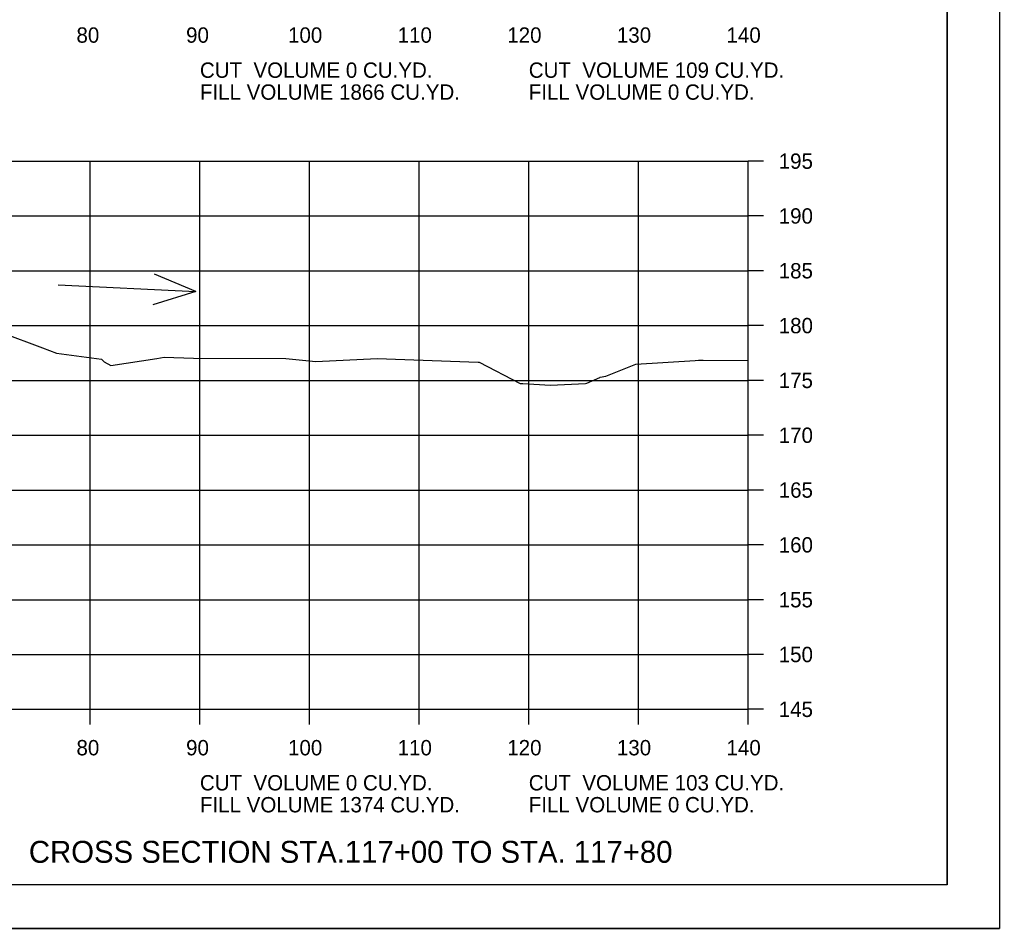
# Model space of a CAD drawing. Extents: x 915787 to 919910, y 133456 to 136717.
# Drawn here: x 916487.5 to 916576.9, y 135376.1 to 135459 of the extents above; entities that cross this region are included whole.
import ezdxf

# ---------------------------------------------------------------- set-up
doc = ezdxf.new("R2010")
doc.units = 0
for name, color, linetype in [('R_Axis', 7, 'Continuous'), ('R_Axis Annot', 7, 'Continuous'), ('R_Border', 7, 'Continuous'), ('R_Border Notes', 7, 'Continuous'), ('R_Draft', 7, 'Continuous'), ('R_Exist Surface', 7, 'Continuous'), ('R_Grid', 7, 'Continuous'), ('R_No Plot', 7, 'Continuous'), ('R_Water Annot', 7, 'Continuous')]:
    doc.layers.add(name, color=color, linetype=linetype)

msp = doc.modelspace()

# ---------------------------------------------------------------- linework, layer by layer
at = {"layer": 'R_Axis'}
for p, q in [((916553.975, 135396.057), (916553.975, 135446.057)), ((916555.375, 135446.057), (916553.975, 135446.057)), ((916555.375, 135441.057), (916553.975, 135441.057)), ((916555.375, 135436.057), (916553.975, 135436.057)), ((916555.375, 135431.057), (916553.975, 135431.057)), ((916555.375, 135426.057), (916553.975, 135426.057)), ((916555.375, 135421.057), (916553.975, 135421.057)), ((916555.375, 135416.057), (916553.975, 135416.057)), ((916555.375, 135411.057), (916553.975, 135411.057)), ((916555.375, 135406.057), (916553.975, 135406.057)), ((916555.375, 135401.057), (916553.975, 135401.057)), ((916273.975, 135396.057), (916553.975, 135396.057)), ((916493.975, 135394.657), (916493.975, 135396.057)), ((916503.975, 135394.657), (916503.975, 135396.057)), ((916513.975, 135394.657), (916513.975, 135396.057)), ((916523.975, 135394.657), (916523.975, 135396.057)), ((916533.975, 135394.657), (916533.975, 135396.057)), ((916543.975, 135394.657), (916543.975, 135396.057)), ((916553.975, 135394.657), (916553.975, 135396.057)), ((916555.375, 135396.057), (916553.975, 135396.057))]:
    msp.add_line(p, q, dxfattribs=at)
at = {"layer": 'R_Border'}
for q in [(916572.155, 135585.517), (916255.975, 135380.057)]:
    msp.add_line((916572.155, 135380.057), q, dxfattribs=at)
at = {"layer": 'R_Exist Surface'}
msp.add_lwpolyline([(916485.868, 135430.421), (916489.603, 135429.03), (916490.895, 135428.535), (916492.276, 135428.352), (916495.004, 135428.001), (916495.249, 135427.761), (916495.854, 135427.424), (916500.053, 135428.049), (916500.729, 135428.163), (916503.38, 135428.085), (916511.82, 135428.063), (916514.557, 135427.779), (916520.138, 135428.043), (916529.345, 135427.733), (916529.421, 135427.72), (916529.437, 135427.713), (916533.178, 135425.785), (916533.427, 135425.766), (916535.942, 135425.629), (916539.15, 135425.79), (916539.272, 135425.791), (916540.449, 135426.326), (916540.493, 135426.342), (916540.998, 135426.437), (916543.747, 135427.546), (916549.153, 135427.878), (916549.447, 135427.89), (916549.882, 135427.898), (916553.975, 135427.869)], dxfattribs=at)
at = {"layer": 'R_Grid'}
for p, q in [((916273.975, 135446.057), (916553.975, 135446.057)), ((916493.975, 135396.057), (916493.975, 135446.057)), ((916503.975, 135396.057), (916503.975, 135446.057)), ((916513.975, 135396.057), (916513.975, 135446.057)), ((916523.975, 135396.057), (916523.975, 135446.057)), ((916533.975, 135396.057), (916533.975, 135446.057)), ((916543.975, 135396.057), (916543.975, 135446.057)), ((916553.975, 135396.057), (916553.975, 135446.057)), ((916273.975, 135441.057), (916553.975, 135441.057)), ((916273.975, 135436.057), (916553.975, 135436.057)), ((916273.975, 135431.057), (916553.975, 135431.057)), ((916273.975, 135426.057), (916553.975, 135426.057)), ((916273.975, 135421.057), (916553.975, 135421.057)), ((916273.975, 135416.057), (916553.975, 135416.057)), ((916273.975, 135411.057), (916553.975, 135411.057)), ((916273.975, 135406.057), (916553.975, 135406.057)), ((916273.975, 135401.057), (916553.975, 135401.057)), ((916273.975, 135396.057), (916553.975, 135396.057))]:
    msp.add_line(p, q, dxfattribs=at)
at = {"layer": 'R_No Plot'}
msp.add_line((916243.574, 135376.078), (916576.908, 135376.078), dxfattribs=at)
for points in [[(916243.568, 135589.411), (916576.908, 135589.411), (916576.908, 135376.074), (916243.568, 135376.074)], [(916489.895, 135585.517), (916489.895, 135575.637), (916525.627, 135575.637), (916525.627, 135572.717), (916548.827, 135572.717), (916548.827, 135549.502), (916572.155, 135549.502), (916572.155, 135380.057), (916255.975, 135380.057), (916255.975, 135585.517)]]:
    msp.add_lwpolyline(points, close=True, dxfattribs=at)
at = {"layer": 'R_Water Annot'}
for p, q in [((916503.594, 135434.167), (916499.819, 135435.75)), ((916491.04, 135434.769), (916503.594, 135434.167)), ((916503.594, 135434.167), (916499.685, 135432.953))]:
    msp.add_line(p, q, dxfattribs=at)

# ---------------------------------------------------------------- texts
at = {"layer": 'R_Axis Annot'}
for s, p in [('80', (916492.714, 135456.857)), ('90', (916502.714, 135456.857)), ('100', (916512.014, 135456.857)), ('110', (916522.014, 135456.857)), ('120', (916532.014, 135456.857)), ('130', (916542.014, 135456.857)), ('140', (916552.014, 135456.857)), ('195', (916556.775, 135445.357)), ('190', (916556.775, 135440.357)), ('185', (916556.775, 135435.357)), ('180', (916556.775, 135430.357)), ('175', (916556.775, 135425.357)), ('170', (916556.775, 135420.357)), ('165', (916556.775, 135415.357)), ('160', (916556.775, 135410.357)), ('155', (916556.775, 135405.357)), ('150', (916556.775, 135400.357)), ('145', (916556.775, 135395.357)), ('80', (916492.714, 135391.857)), ('90', (916502.714, 135391.857)), ('100', (916512.014, 135391.857)), ('110', (916522.014, 135391.857)), ('120', (916532.014, 135391.857)), ('130', (916542.014, 135391.857)), ('140', (916552.014, 135391.857))]:
    msp.add_text(s, height=1.4, dxfattribs=at).set_placement(p)
at = {"layer": 'R_Border Notes'}
for s, p in [('CUT  VOLUME 0 CU.YD.', (916503.975, 135453.657)), ('CUT  VOLUME 109 CU.YD.', (916533.975, 135453.657)), ('FILL VOLUME 1866 CU.YD.', (916503.975, 135451.657)), ('FILL VOLUME 0 CU.YD.', (916533.975, 135451.657)), ('CUT  VOLUME 0 CU.YD.', (916503.975, 135388.657)), ('CUT  VOLUME 103 CU.YD.', (916533.975, 135388.657)), ('FILL VOLUME 1374 CU.YD.', (916503.975, 135386.657)), ('FILL VOLUME 0 CU.YD.', (916533.975, 135386.657))]:
    msp.add_text(s, height=1.4, dxfattribs=at).set_placement(p)
at = {"layer": 'R_Draft'}
msp.add_text('CROSS SECTION STA.117+00 TO STA. 117+80', height=2, dxfattribs=at).set_placement((916488.371, 135382.057))

doc.saveas('drawing.dxf')
